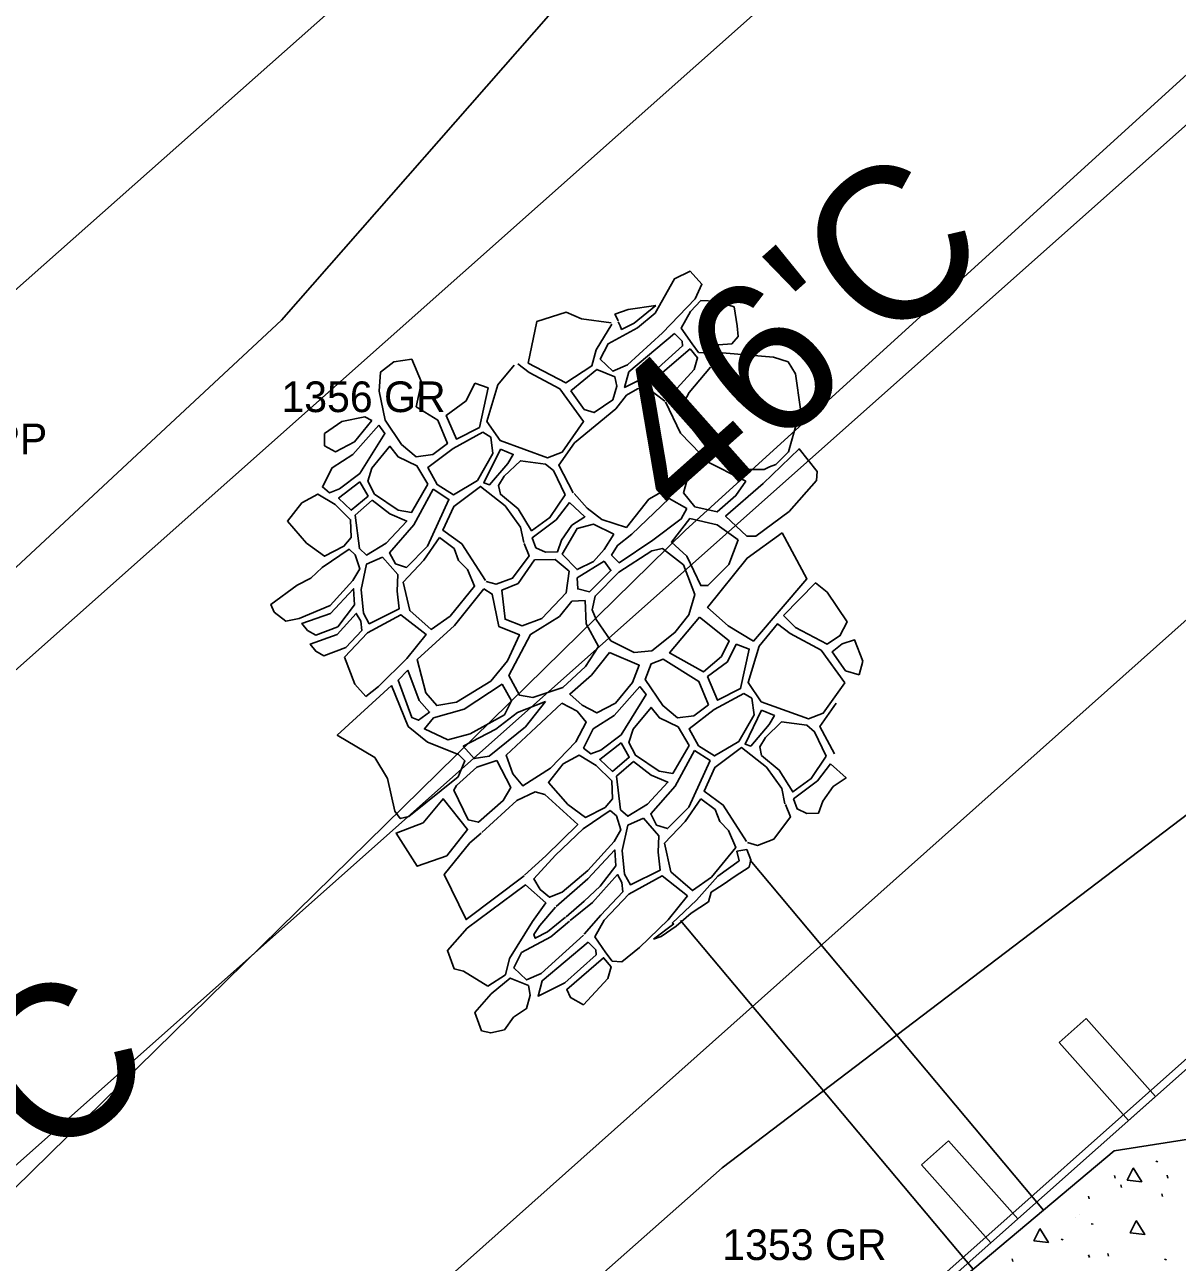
# Model space of a CAD drawing. Extents: x 49683 to 58852, y 49525 to 54803.
# Drawn here: x 53900.13 to 53937.68, y 51884.59 to 51924.92 of the extents above; entities that cross this region are included whole.
import ezdxf

# ---------------------------------------------------------------- set-up
doc = ezdxf.new("R2010")
doc.units = 0
for name, color, linetype in [('Level 1', 7, 'Continuous'), ('Level 11', 7, 'Continuous'), ('Level 16', 7, 'Continuous'), ('Level 18', 7, 'Continuous'), ('Level 27', 7, 'Continuous'), ('Level 3', 7, 'Continuous'), ('Level 48', 7, 'Continuous'), ('Level 57', 7, 'Continuous'), ('Level 59', 7, 'Continuous'), ('Level 7', 7, 'Continuous'), ('Level 8', 7, 'Continuous')]:
    doc.layers.add(name, color=color, linetype=linetype)

msp = doc.modelspace()

# ---------------------------------------------------------------- linework, layer by layer
at = {"layer": 'Level 1'}
msp.add_line((52544.807, 50683.302), (55534.583, 53340.862), dxfattribs=at)
at = {"layer": 'Level 11'}
msp.add_line((53894.91, 51911.927), (54324.203, 52292.615), dxfattribs=at)
at = {"layer": 'Level 16'}
for p, q in [((53923.325, 51897.993), (53923.656, 51898.041)), ((53923.656, 51898.041), (53923.782, 51897.709)), ((53922.709, 51897.172), (53923.403, 51897.677)), ((53923.403, 51897.677), (53923.325, 51897.993)), ((53923.782, 51897.709), (53923.735, 51897.472)), ((53923.735, 51897.472), (53923.277, 51897.172)), ((53922.014, 51896.397), (53922.709, 51897.172)), ((53922.882, 51896.903), (53922.488, 51896.65)), ((53923.277, 51897.172), (53922.882, 51896.903)), ((53922.488, 51896.65), (53922.409, 51896.334)), ((53921.225, 51895.639), (53922.014, 51896.397)), ((53922.409, 51896.334), (53921.84, 51895.97)), ((53920.609, 51895.117), (53921.272, 51895.623)), ((53921.272, 51895.623), (53921.225, 51895.639)), ((53921.84, 51895.97), (53921.351, 51895.544)), ((53921.351, 51895.544), (53920.861, 51895.212)), ((53920.861, 51895.212), (53920.609, 51895.117))]:
    msp.add_line(p, q, dxfattribs=at)
for points in [[(53920.663, 51915.527), (53921.297, 51916.644), (53921.805, 51916.891), (53922.188, 51916.466), (53921.968, 51915.993), (53920.907, 51914.878)], [(53922.152, 51915.935), (53921.818, 51915.582), (53921.515, 51915.034), (53921.872, 51914.52), (53922.084, 51914.241), (53922.397, 51914.219), (53922.734, 51914.491)], [(53922.152, 51915.935), (53922.639, 51915.912), (53923.236, 51915.727), (53923.335, 51915.11), (53923.376, 51914.761), (53923.165, 51914.529), (53922.734, 51914.491)], [(53916.531, 51913.893), (53916.806, 51915.251), (53917.767, 51915.561), (53918.262, 51915.334), (53919.236, 51915.208)], [(53920.663, 51915.527), (53920.089, 51915.042), (53919.133, 51914.527), (53918.875, 51914.024), (53919.291, 51913.632), (53919.769, 51913.841), (53920.907, 51914.878)], [(53919.463, 51915.272), (53919.414, 51915.368), (53919.357, 51915.487), (53919.785, 51915.644), (53920.688, 51915.777)], [(53919.463, 51915.243), (53919.525, 51915.115), (53919.574, 51914.993), (53919.979, 51915.201), (53920.688, 51915.777)], [(53920.649, 51915.752), (53920.58, 51915.692)], [(53916.531, 51913.893), (53917.759, 51913.251), (53918.605, 51913.803), (53918.74, 51914.33), (53919.256, 51915.166)], [(53922.489, 51913.783), (53922.845, 51914.23)], [(53924.393, 51910.513), (53924.597, 51910.588), (53925.009, 51911.007), (53925.398, 51912.39), (53925.238, 51913.545), (53924.997, 51913.943), (53924.52, 51914.087), (53922.845, 51914.23)], [(53911.864, 51912.039), (53911.674, 51912.978), (53911.719, 51913.601), (53912.149, 51913.935), (53912.737, 51914.029), (53913.058, 51913.271), (53912.88, 51912.467)], [(53916.074, 51913.829), (53915.541, 51913.187), (53915.185, 51911.998), (53915.613, 51911.374), (53917.156, 51910.812), (53917.634, 51910.996), (53918.333, 51911.99), (53917.563, 51913.055), (53916.559, 51913.593), (53916.187, 51913.876)], [(53924.393, 51910.513), (53924.214, 51910.427), (53923.626, 51910.427), (53922.367, 51911.118), (53921.654, 51912.041), (53921.539, 51912.492), (53921.771, 51912.933), (53922.473, 51913.768)], [(53920.982, 51912.658), (53920.442, 51913.07), (53920.087, 51913.057), (53919.731, 51912.849), (53919.388, 51912.407), (53918.039, 51911.303), (53917.523, 51910.567), (53918, 51909.672)], [(53921.008, 51912.632), (53921.496, 51911.61), (53922.146, 51910.939), (53921.243, 51909.909), (53920.455, 51909.457), (53919.729, 51908.543), (53918.932, 51908.794), (53918.449, 51909.171), (53918.026, 51909.646)], [(53911.864, 51912.039), (53912.403, 51911.248), (53912.88, 51910.844), (53913.419, 51910.918), (53913.897, 51911.274), (53913.58, 51912.033), (53912.88, 51912.467)], [(53909.896, 51911.196), (53909.897, 51911.601), (53910.461, 51911.997), (53911.207, 51912.149)], [(53909.896, 51911.196), (53910.256, 51911.009), (53910.868, 51911.325), (53911.434, 51912.022)], [(53911.207, 51912.149), (53911.434, 51912.022)], [(53924.191, 51909.973), (53925.358, 51911.106), (53925.948, 51910.362), (53925.923, 51910.069), (53925.029, 51909.06)], [(53916.383, 51908.049), (53916.283, 51908.544), (53915.782, 51909.242), (53914.974, 51909.878), (53914.103, 51909.228), (53913.747, 51908.456), (53914.371, 51908.003), (53915.134, 51906.813)], [(53924.191, 51909.973), (53922.963, 51908.904), (53923.655, 51908.254), (53923.949, 51908.254), (53925.029, 51909.06)], [(53908.684, 51908.742), (53909.309, 51908.027), (53909.889, 51907.604), (53910.526, 51907.928), (53910.761, 51908.208), (53910.74, 51908.789), (53910.238, 51909.291), (53909.679, 51909.626), (53909.154, 51909.346), (53908.684, 51908.742)], [(53910.078, 51905.997), (53910.816, 51906.811), (53911.04, 51907.191), (53910.895, 51907.649), (53910.694, 51907.828), (53909.811, 51907.235), (53909.448, 51906.89)], [(53916.398, 51908.022), (53916.56, 51907.616), (53916.022, 51906.889), (53915.484, 51906.688), (53915.161, 51906.784)], [(53910.078, 51905.997), (53909.064, 51905.575), (53908.631, 51905.491), (53908.248, 51905.781), (53908.147, 51906.03), (53909.002, 51906.664), (53909.448, 51906.89)], [(53910.092, 51905.74), (53910.838, 51906.543), (53910.871, 51906.018), (53910.325, 51905.303)], [(53924.849, 51905.67), (53925.892, 51906.732), (53926.271, 51906.43), (53926.922, 51905.469), (53926.688, 51905.003)], [(53910.325, 51905.303), (53909.605, 51905.031), (53909.339, 51905.178), (53909.158, 51905.41), (53910.092, 51905.74)], [(53910.584, 51904.628), (53911.104, 51905.181), (53911.071, 51905.482), (53910.926, 51905.739), (53910.303, 51905.048)], [(53911.242, 51903.031), (53911.65, 51903.36), (53912.578, 51904.266), (53913.205, 51905.049), (53912.378, 51905.696), (53911.294, 51905.103), (53910.547, 51904.314)], [(53924.849, 51905.67), (53925.242, 51905.277), (53926.27, 51904.739), (53926.708, 51905.025)], [(53910.584, 51904.628), (53909.874, 51904.359), (53909.608, 51904.506), (53909.426, 51904.738), (53910.303, 51905.048)], [(53926.755, 51904.751), (53926.429, 51904.482), (53926.87, 51903.87), (53927.315, 51903.734)], [(53926.755, 51904.751), (53927.157, 51904.882), (53927.438, 51904.183), (53927.315, 51903.734)], [(53910.547, 51904.314), (53910.882, 51903.436), (53911.242, 51903.031)], [(53912.079, 51903.394), (53910.308, 51901.775), (53911.528, 51901.045), (53911.943, 51900.353), (53912.184, 51899.292), (53912.36, 51899.052), (53912.636, 51899.124)], [(53912.079, 51903.394), (53912.623, 51902.058), (53913.244, 51901.542), (53914.255, 51901.143), (53914.466, 51900.932), (53914.244, 51900.416), (53912.636, 51899.124)], [(53926.569, 51902.818), (53926.035, 51902.056), (53926.511, 51901.161)], [(53924.894, 51899.538), (53924.795, 51900.033), (53924.293, 51900.731), (53923.485, 51901.367), (53922.615, 51900.717), (53922.259, 51899.944), (53922.883, 51899.492), (53923.645, 51898.302)], [(53913.883, 51897.836), (53914.553, 51898.691), (53913.757, 51899.697), (53913.108, 51898.916)], [(53916.412, 51897.203), (53917.103, 51897.839), (53918.143, 51898.857), (53917.072, 51899.839), (53916.759, 51899.928), (53916.156, 51899.637), (53915.017, 51898.597)], [(53924.909, 51899.511), (53925.072, 51899.105), (53924.533, 51898.377), (53923.996, 51898.176), (53923.672, 51898.273)], [(53913.883, 51897.836), (53912.915, 51897.5), (53912.222, 51898.58), (53913.108, 51898.916)], [(53915, 51898.581), (53914.628, 51898.262), (53913.794, 51897.232), (53914.503, 51895.762), (53916.394, 51897.186)], [(53917.442, 51896.191), (53918.477, 51897.092), (53919.349, 51898.032), (53919.382, 51897.507), (53918.879, 51896.847), (53918.353, 51896.366), (53917.763, 51895.851)], [(53915.213, 51893.588), (53915.788, 51893.963), (53915.923, 51894.49), (53916.672, 51895.703), (53917.101, 51896.304), (53916.44, 51896.892), (53914.545, 51895.478)], [(53918.354, 51895.28), (53918.9, 51895.909), (53919.616, 51896.669), (53919.583, 51896.971), (53919.438, 51897.227), (53918.621, 51896.322), (53917.898, 51895.735)], [(53917.417, 51896.166), (53916.904, 51895.569), (53916.708, 51895.275), (53916.757, 51895.152), (53917.161, 51895.361), (53917.744, 51895.834)], [(53917.873, 51895.71), (53917.271, 51895.202), (53916.315, 51894.686), (53916.057, 51894.183), (53916.473, 51893.792), (53916.951, 51894.001), (53918.328, 51895.255)], [(53915.213, 51893.588), (53914.421, 51894.081), (53914.118, 51894.153), (53913.895, 51894.75), (53914.545, 51895.478)], [(53918.335, 51892.985), (53919.12, 51893.844), (53919.231, 51894.224), (53918.986, 51894.518), (53917.784, 51893.487), (53917.906, 51893.218), (53918.335, 51892.985)], [(53916.056, 51892.577), (53916.472, 51892.861), (53916.595, 51893.302), (53916.534, 51893.608), (53915.947, 51893.853), (53915.324, 51893.338)], [(53916.056, 51892.577), (53915.757, 51892.172), (53915.312, 51892.066), (53915.008, 51892.138), (53914.786, 51892.735), (53915.324, 51893.338)]]:
    msp.add_lwpolyline(points, dxfattribs=at)
for points in [[(53921.302, 51914.86), (53919.805, 51913.608), (53919.67, 51913.106), (53920.54, 51913.536), (53921.558, 51914.456), (53921.546, 51914.615)], [(53921.803, 51914.358), (53920.601, 51913.328), (53920.724, 51913.058), (53921.152, 51912.826), (53921.937, 51913.684), (53922.048, 51914.064)], [(53917.918, 51912.994), (53918.358, 51912.382), (53918.677, 51912.284), (53919.29, 51912.701), (53919.413, 51913.142), (53919.352, 51913.449), (53918.764, 51913.693)], [(53914.794, 51913.247), (53915.223, 51913.089), (53914.939, 51911.802), (53914.192, 51911.421), (53913.862, 51912.193), (53914.512, 51912.671)], [(53911.659, 51911.873), (53910.82, 51910.923), (53910.138, 51910.486), (53909.825, 51909.86), (53910.059, 51909.671), (53910.383, 51909.794), (53911.043, 51910.297), (53911.86, 51911.606)], [(53915.049, 51911.643), (53914.081, 51911.115), (53913.259, 51910.489), (53913.565, 51909.938), (53914.092, 51909.608), (53914.876, 51910.074), (53915.379, 51910.945), (53915.307, 51911.484)], [(53913.259, 51909.95), (53912.904, 51910.55), (53912.292, 51910.843), (53912.023, 51911.186), (53911.434, 51910.475), (53911.299, 51910.046), (53911.519, 51909.629), (53912.29, 51909.103), (53912.731, 51909.03)], [(53915.625, 51911.092), (53915.084, 51909.989), (53915.268, 51909.928), (53915.869, 51910.627), (53916.041, 51910.921)], [(53917.73, 51909.6), (53917.239, 51908.864), (53916.639, 51908.435), (53916.198, 51909.145), (53915.623, 51909.622), (53915.562, 51909.903), (53915.746, 51910.21), (53916.274, 51910.713), (53917.094, 51910.604), (53917.351, 51910.396)], [(53923.626, 51910.049), (53922.283, 51910.719), (53921.715, 51910.13), (53921.589, 51909.668), (53921.956, 51909.217), (53922.69, 51909.05), (53923.3, 51909.576)], [(53911.043, 51910.029), (53910.349, 51909.492), (53910.762, 51909.102), (53911.31, 51909.56)], [(53913.433, 51909.786), (53912.806, 51908.624), (53912.012, 51907.718), (53912.202, 51907.349), (53912.559, 51907.238), (53913.252, 51907.931), (53913.947, 51909.452)], [(53911.444, 51909.426), (53910.896, 51908.945), (53911.029, 51907.851), (53911.264, 51907.639), (53911.901, 51908.03), (53912.572, 51908.746), (53912.025, 51908.98)], [(53917.872, 51909.349), (53917.441, 51908.792), (53916.664, 51908.204), (53916.779, 51907.878), (53917.094, 51907.732), (53917.482, 51907.743), (53917.619, 51908.131), (53917.955, 51908.614), (53918.376, 51908.888)], [(53921.704, 51909.154), (53921.127, 51909.479), (53919.908, 51908.323), (53919.435, 51907.955), (53919.246, 51907.64), (53919.497, 51907.388), (53920.59, 51908.124), (53921.514, 51908.818)], [(53919.32, 51908.322), (53918.659, 51908.647), (53918.123, 51908.51), (53917.639, 51907.669), (53918.122, 51907.166), (53918.657, 51907.429), (53919.004, 51907.818)], [(53923.371, 51908.138), (53922.69, 51908.63), (53921.798, 51908.829), (53921.198, 51908.062), (53921.702, 51907.601), (53922.152, 51906.646), (53922.383, 51906.646), (53923.066, 51907.329)], [(53913.644, 51908.211), (53913.129, 51907.473), (53912.458, 51906.757), (53912.669, 51905.83), (53913.372, 51905.217), (53913.987, 51905.653), (53914.782, 51906.626), (53914.548, 51907.173), (53914.258, 51907.463), (53914.113, 51907.854)], [(53924.804, 51908.364), (53923.664, 51907.542), (53922.376, 51905.936), (53923.049, 51905.336), (53923.869, 51904.835), (53925.611, 51906.87)], [(53920.904, 51907.852), (53920.558, 51907.778), (53919.486, 51907.084), (53918.709, 51906.306), (53918.614, 51905.855), (53918.739, 51905.54), (53919.221, 51904.847), (53919.987, 51904.46), (53920.554, 51904.524), (53921.311, 51905.112), (53921.763, 51905.69), (53921.963, 51906.352), (53921.586, 51907.317)], [(53911.777, 51907.572), (53911.263, 51907.348), (53911.083, 51906.521), (53911.161, 51905.75), (53911.35, 51905.404), (53912.323, 51905.886), (53912.256, 51906.467), (53912.279, 51907.003)], [(53916.739, 51907.48), (53916.201, 51906.71), (53915.674, 51906.498), (53915.778, 51905.55), (53916.336, 51905.329), (53916.979, 51905.572), (53917.771, 51906.406), (53917.866, 51907.112), (53917.403, 51907.491)], [(53919.004, 51907.44), (53918.121, 51906.893), (53918.142, 51906.536), (53918.53, 51906.442), (53919.224, 51907.136)], [(53915.084, 51906.54), (53915.357, 51906.371), (53915.577, 51905.307), (53916.241, 51905.045), (53915.85, 51904.19), (53915.312, 51903.526), (53914.194, 51902.85), (53913.551, 51902.733), (53913.193, 51903.155), (53912.91, 51904.24), (53914.123, 51905.348)], [(53917.95, 51906.142), (53917.549, 51905.636), (53916.61, 51905.055), (53915.902, 51903.716), (53916.249, 51903.074), (53916.681, 51903.001), (53917.662, 51903.328), (53918.4, 51904.004), (53918.823, 51904.658), (53918.423, 51905.395), (53918.382, 51906.154)], [(53922.106, 51905.617), (53921.137, 51904.452), (53922.239, 51903.84), (53922.827, 51904.331), (53923.073, 51904.846)], [(53926.845, 51903.478), (53926.074, 51904.543), (53925.07, 51905.081), (53924.654, 51905.399), (53924.053, 51904.676), (53923.696, 51903.487), (53924.124, 51902.862), (53925.667, 51902.3), (53926.145, 51902.485)], [(53923.305, 51904.736), (53923.734, 51904.577), (53923.451, 51903.29), (53922.703, 51902.91), (53922.373, 51903.681), (53923.023, 51904.16)], [(53919.181, 51904.468), (53918.59, 51903.73), (53917.883, 51903.107), (53918.283, 51902.749), (53918.767, 51902.497), (53919.379, 51902.814), (53919.928, 51903.489), (53920.15, 51904.048)], [(53922.409, 51902.762), (53922.091, 51903.522), (53920.928, 51904.243), (53920.536, 51904.096), (53920.339, 51903.581), (53920.914, 51902.736), (53921.391, 51902.332), (53921.931, 51902.406)], [(53912.604, 51903.892), (53912.982, 51902.901), (53913.319, 51902.522), (53912.95, 51902.258), (53912.739, 51902.343), (53912.298, 51903.565)], [(53915.681, 51903.431), (53915.986, 51902.894), (53915.753, 51902.43), (53914.636, 51901.818), (53913.908, 51901.617), (53913.15, 51901.974), (53913.445, 51902.333), (53914.447, 51902.619)], [(53920.171, 51903.362), (53919.332, 51902.411), (53918.65, 51901.975), (53918.336, 51901.349), (53918.571, 51901.159), (53918.895, 51901.282), (53919.555, 51901.786), (53920.372, 51903.094)], [(53923.561, 51903.131), (53922.592, 51902.603), (53921.771, 51901.977), (53922.077, 51901.427), (53922.603, 51901.096), (53923.388, 51901.563), (53923.891, 51902.433), (53923.818, 51902.972)], [(53917.092, 51902.864), (53916.185, 51902.505), (53915.479, 51901.966), (53914.414, 51901.407), (53914.772, 51901.006), (53915.256, 51901.091), (53916.438, 51902.041)], [(53917.63, 51902.812), (53918.125, 51902.549), (53918.419, 51902.191), (53918.081, 51901.558), (53917.258, 51900.693), (53916.351, 51900.123), (53916.025, 51900.513), (53915.815, 51901.124), (53916.786, 51902.031)], [(53921.77, 51901.438), (53921.416, 51902.038), (53920.803, 51902.332), (53920.534, 51902.674), (53919.945, 51901.963), (53919.81, 51901.534), (53920.03, 51901.118), (53920.801, 51900.592), (53921.242, 51900.519)], [(53924.136, 51902.581), (53923.596, 51901.477), (53923.78, 51901.416), (53924.381, 51902.115), (53924.553, 51902.409)], [(53926.242, 51901.088), (53925.751, 51900.353), (53925.15, 51899.923), (53924.71, 51900.633), (53924.134, 51901.11), (53924.074, 51901.392), (53924.258, 51901.699), (53924.785, 51902.201), (53925.606, 51902.092), (53925.863, 51901.884)], [(53919.554, 51901.518), (53918.861, 51900.981), (53919.274, 51900.59), (53919.822, 51901.049)], [(53921.945, 51901.275), (53921.318, 51900.112), (53920.524, 51899.206), (53920.713, 51898.838), (53921.07, 51898.726), (53921.764, 51899.42), (53922.458, 51900.94)], [(53915.509, 51900.944), (53914.856, 51900.733), (53914.191, 51900.131), (53914.106, 51899.983), (53914.569, 51899.014), (53914.906, 51898.931), (53915.719, 51899.638), (53915.961, 51900.07)], [(53919.273, 51899.696), (53919.251, 51900.277), (53918.749, 51900.78), (53918.191, 51901.114), (53917.665, 51900.834), (53917.195, 51900.23), (53917.82, 51899.516), (53918.401, 51899.092), (53919.038, 51899.417)], [(53919.956, 51900.915), (53919.408, 51900.434), (53919.541, 51899.339), (53919.775, 51899.127), (53920.412, 51899.519), (53921.083, 51900.235), (53920.536, 51900.469)], [(53926.384, 51900.838), (53925.953, 51900.281), (53925.175, 51899.692), (53925.29, 51899.367), (53925.605, 51899.22), (53925.994, 51899.231), (53926.13, 51899.62), (53926.467, 51900.103), (53926.887, 51900.376)], [(53922.155, 51899.7), (53921.641, 51898.962), (53920.969, 51898.246), (53921.181, 51897.319), (53921.884, 51896.705), (53922.499, 51897.142), (53923.293, 51898.114), (53923.059, 51898.662), (53922.769, 51898.952), (53922.624, 51899.343)], [(53919.205, 51899.316), (53918.322, 51898.723), (53917.416, 51897.862), (53916.711, 51897.09), (53916.923, 51896.744), (53917.225, 51896.488), (53917.638, 51896.656), (53918.477, 51897.36), (53919.327, 51898.3), (53919.551, 51898.68), (53919.406, 51899.138)], [(53920.289, 51899.061), (53919.775, 51898.837), (53919.595, 51898.01), (53919.672, 51897.239), (53919.862, 51896.893), (53920.834, 51897.374), (53920.768, 51897.955), (53920.791, 51898.492)], [(53921.716, 51896.537), (53920.89, 51897.184), (53919.806, 51896.591), (53919, 51895.741), (53918.698, 51895.193), (53919.055, 51894.68), (53919.267, 51894.401), (53919.58, 51894.379), (53920.161, 51894.849), (53921.089, 51895.755)], [(53918.484, 51895.019), (53916.988, 51893.768), (53916.853, 51893.265), (53917.723, 51893.695), (53918.741, 51894.615), (53918.729, 51894.775)]]:
    msp.add_lwpolyline(points, close=True, dxfattribs=at)
at = {"layer": 'Level 18'}
for p, q in [((53921.658, 51908.457), (53958.658, 51942.092)), ((53894.5, 51881.812), (53921.658, 51908.457))]:
    msp.add_line(p, q, dxfattribs=at)
at = {"layer": 'Level 27'}
for p, q in [((53909.014, 51865.483), (53951.064, 51902.86)), ((53909.18, 51865.296), (53951.23, 51902.673)), ((53933.829, 51891.755), (53934.712, 51892.54)), ((53934.712, 51892.54), (53936.971, 51889.999)), ((53936.087, 51889.213), (53933.829, 51891.755)), ((53936.971, 51889.999), (53936.087, 51889.213)), ((53929.344, 51887.769), (53930.228, 51888.554)), ((53930.228, 51888.554), (53932.486, 51886.012)), ((53931.603, 51885.227), (53929.344, 51887.769)), ((53932.486, 51886.012), (53931.603, 51885.227))]:
    msp.add_line(p, q, dxfattribs=at)
at = {"layer": 'Level 3'}
for p, q in [((53883.273, 51889.178), (54069.537, 52054.718)), ((53898.742, 51870.567), (54083.389, 52035.124))]:
    msp.add_line(p, q, dxfattribs=at)
at = {"layer": 'Level 7'}
for p, q in [((53934.082, 51944.47), (53908.487, 51915.299)), ((53908.487, 51915.299), (53883.022, 51891.572)), ((53922.854, 51887.665), (53958.852, 51915.059)), ((53902.065, 51869.327), (53922.854, 51887.665))]:
    msp.add_line(p, q, dxfattribs=at)
at = {"layer": 'Level 8'}
for p, q in [((53933.325, 51886.292), (53923.765, 51897.699)), ((53931.026, 51884.365), (53921.496, 51895.735)), ((53935.625, 51888.219), (53953.195, 51891.04)), ((53924.129, 51878.584), (53935.625, 51888.219)), ((53937.045, 51887.867), (53936.981, 51887.886)), ((53935.631, 51887.423), (53935.655, 51887.336)), ((53937.348, 51887.426), (53937.372, 51887.338)), ((53935.843, 51887.113), (53935.867, 51887.025)), ((53937.175, 51886.819), (53937.199, 51886.731)), ((53934.789, 51886.743), (53934.813, 51886.655)), ((53934.374, 51886.047), (53934.374, 51886.047)), ((53934.503, 51886.153), (53934.503, 51886.153)), ((53934.939, 51885.83), (53934.875, 51885.849)), ((53933.956, 51885.326), (53933.892, 51885.346)), ((53934.79, 51884.834), (53934.814, 51884.746)), ((53935.412, 51884.878), (53935.437, 51884.79)), ((53932.296, 51884.701), (53932.321, 51884.614)), ((53937.327, 51884.668), (53937.263, 51884.688))]:
    msp.add_line(p, q, dxfattribs=at)
for points in [[(53936.245, 51887.669), (53936.524, 51887.214), (53936.051, 51887.268), (53936.24, 51887.661)], [(53936.342, 51885.951), (53936.621, 51885.496), (53936.148, 51885.55), (53936.337, 51885.943)], [(53933.202, 51885.692), (53933.481, 51885.237), (53933.008, 51885.291), (53933.197, 51885.684)]]:
    msp.add_lwpolyline(points, dxfattribs=at)

# ---------------------------------------------------------------- texts
at = {"layer": 'Level 48'}
for s, p in [("46'C", (53921.658, 51908.457)), ("44'C", (53894.5, 51881.812))]:
    msp.add_text(s, height=5, rotation=41.6334, dxfattribs=at).set_placement(p)
at = {"layer": 'Level 57'}
for s, p in [('1356 GR', (53908.487, 51912.299)), ('1353 GR', (53922.854, 51884.665))]:
    msp.add_text(s, height=1, dxfattribs=at).set_placement(p)
at = {"layer": 'Level 59'}
msp.add_text('1359 TPP', height=1, dxfattribs=at).set_placement((53894.91, 51910.927))

doc.saveas('drawing.dxf')
